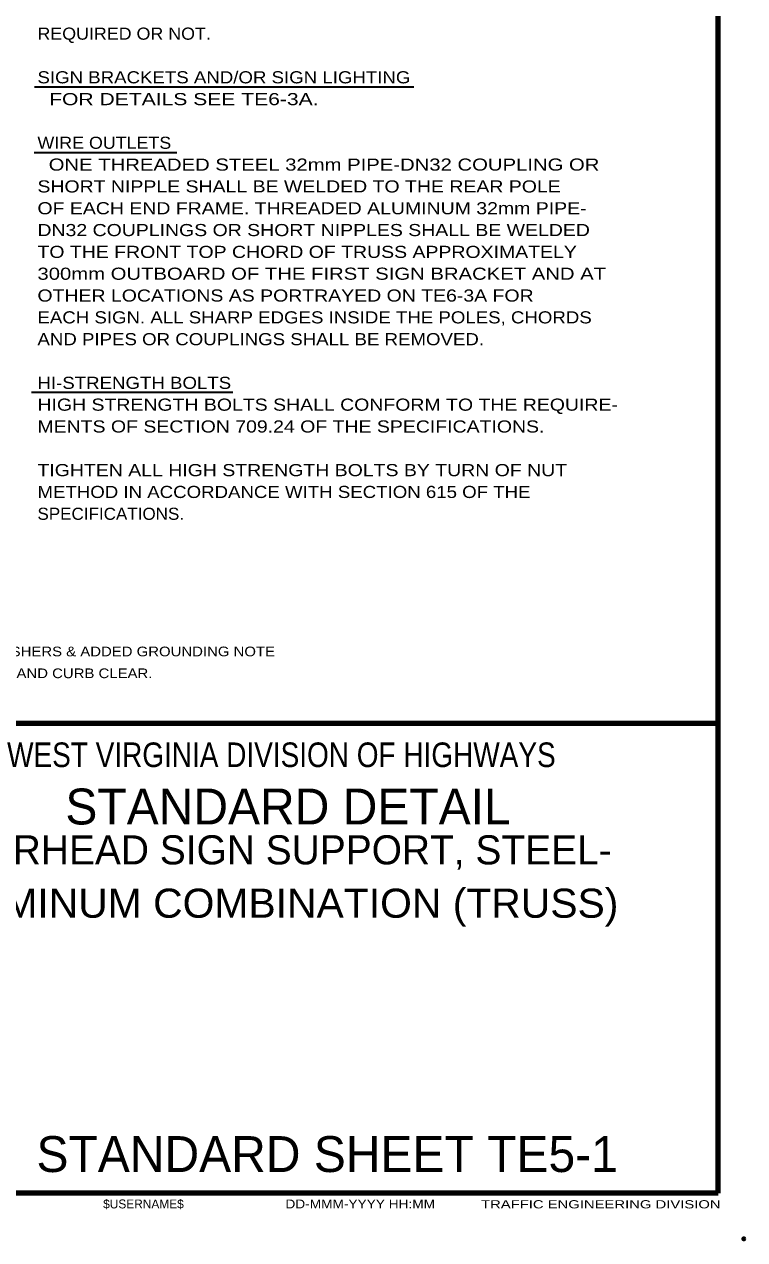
# Model space of a CAD drawing. Extents: x -29 to 827, y -14 to 530.
# Drawn here: x 648.3 to 826.6, y -14.4 to 286.3 of the extents above; entities that cross this region are included whole.
import ezdxf
from ezdxf.enums import TextEntityAlignment as Align

# ---------------------------------------------------------------- set-up
doc = ezdxf.new("R2010")
doc.units = 0
doc.header["$LTSCALE"] = 0.97
doc.header["$PDMODE"] = 32
doc.header["$PDSIZE"] = 0.485
doc.layers.add('1', color=7, linetype='Continuous', lineweight=53)
doc.layers.add('61', color=7, linetype='Continuous', lineweight=35)

msp = doc.modelspace()

# ---------------------------------------------------------------- linework, layer by layer
at = {"layer": '1', "lineweight": 158}
for q in [(820.0407, 523.2545), (820.0407, 113.4545), (28.4407, -2.8455)]:
    msp.add_line((820.0407, -2.8455), q, dxfattribs=at)
at = {"layer": '1', "lineweight": 13}
msp.add_line((820.0407, -2.8455), (820.0407, 523.2545), dxfattribs=at)
at = {"layer": '1', "lineweight": 35}
for p, q in [((650.8375, 270.8736), (744.7366, 270.8736)), ((650.7447, 254.6211), (686.0446, 254.6211)), ((650.1141, 195.3366), (699.919, 195.3366))]:
    msp.add_line(p, q, dxfattribs=at)
at = {"layer": '1', "lineweight": 158}
msp.add_lwpolyline([(602.0407, -2.8455), (602.0407, 113.4545), (820.0407, 113.4545)], dxfattribs=at)
at = {"layer": '1'}
msp.add_point((826.3407, -14.1455), dxfattribs=at)
at = {"layer": '61', "lineweight": 53}
for q in [(667.3407, -2.8455), (667.3407, -2.8455), (667.3407, -2.8455), (667.6407, -2.8455), (667.6407, -2.8455)]:
    msp.add_line((820.0407, -2.8455), q, dxfattribs=at)

# ---------------------------------------------------------------- texts
at = {"layer": '1'}
for s, height, width, p in [('REQUIRED OR NOT.', 3, 1.1, (651.5801, 282.532)), ('SIGN BRACKETS AND/OR SIGN LIGHTING', 3, 1.15, (651.5801, 271.732)), ('  FOR DETAILS SEE TE6-3A.', 3, 1.3, (651.5801, 266.332)), ('WIRE OUTLETS', 3, 1.1, (651.5801, 255.532)), ('  ONE THREADED STEEL 32mm PIPE-DN32 COUPLING OR', 3, 1.25, (651.5801, 250.132)), ('SHORT NIPPLE SHALL BE WELDED TO THE REAR POLE', 3, 1.2, (651.5801, 244.732)), ('OF EACH END FRAME. THREADED ALUMINUM 32mm PIPE-', 3, 1.2, (651.5801, 239.332)), ('DN32 COUPLINGS OR SHORT NIPPLES SHALL BE WELDED', 3, 1.2, (651.5801, 233.932)), ('TO THE FRONT TOP CHORD OF TRUSS APPROXIMATELY', 3, 1.2, (651.5801, 228.532)), ('300mm OUTBOARD OF THE FIRST SIGN BRACKET AND AT', 3, 1.25, (651.5801, 223.132)), ('OTHER LOCATIONS AS PORTRAYED ON TE6-3A FOR', 3, 1.2, (651.5801, 217.732)), ('EACH SIGN. ALL SHARP EDGES INSIDE THE POLES, CHORDS', 3, 1.15, (651.5801, 212.332)), ('AND PIPES OR COUPLINGS SHALL BE REMOVED.', 3, 1.15, (651.5801, 206.932)), ('HI-STRENGTH BOLTS', 3, 1.15, (651.5801, 196.132)), ('HIGH STRENGTH BOLTS SHALL CONFORM TO THE REQUIRE-', 3, 1.2, (651.5801, 190.732)), ('MENTS OF SECTION 709.24 OF THE SPECIFICATIONS.', 3, 1.2, (651.5801, 185.332)), ('TIGHTEN ALL HIGH STRENGTH BOLTS BY TURN OF NUT', 3, 1.2, (651.5801, 174.532)), ('METHOD IN ACCORDANCE WITH SECTION 615 OF THE', 3, 1.15, (651.5801, 169.132)), ('SPECIFICATIONS.', 3, 1.05, (651.5801, 163.732)), ('DELETED LOCK WASHERS & ADDED GROUNDING NOTE', 2.4, 1.15, (609.8827, 129.9598)), ('ADDED GUARDRAIL AND CURB CLEAR.', 2.4, 1.15, (609.8927, 124.5557)), ('DD-MMM-YYYY HH:MM', 2.2, 1.15, (712.9407, -6.6455)), ('TRAFFIC ENGINEERING DIVISION', 2.031, 1.35, (761.3407, -6.6455))]:
    msp.add_text(s, height=height, dxfattribs=dict(at, width=width)).set_placement(p)
for s, height, width, p in [('WEST VIRGINIA DIVISION OF HIGHWAYS', 6.089, 0.85, (711.9407, 102.5545)), ('ALUMINUM COMBINATION (TRUSS)', 7.2, 1.05, (709.4043, 65.2732))]:
    msp.add_text(s, height=height, dxfattribs=dict(at, width=width)).set_placement(p, align=Align.CENTER)
for s, height, p in [('STANDARD DETAIL', 8.881, (713.5907, 88.3545)), ('OVERHEAD SIGN SUPPORT, STEEL-', 7.2, (709.4042, 78.4732))]:
    msp.add_text(s, height=height, dxfattribs=at).set_placement(p, align=Align.CENTER)
for s, height, p in [('STANDARD SHEET TE5-1 ', 8.881, (651.3407, 2.3545)), ('$USERNAME$', 2.2, (667.8407, -6.6455))]:
    msp.add_text(s, height=height, dxfattribs=at).set_placement(p)

doc.saveas('drawing.dxf')
